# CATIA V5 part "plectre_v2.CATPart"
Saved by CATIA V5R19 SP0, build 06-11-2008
Part number: plectre_v2
Bounding box of the stored display mesh (mm): x 0 to 29, y 0 to 25.001, z 0 to 25.001
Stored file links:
  C:\Users\Rémi\Documents\BTS CPI\Projet 04- Guitar Elec\Maquette 3D\Système Médiator\plectre_v2.CATPart
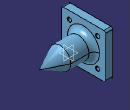
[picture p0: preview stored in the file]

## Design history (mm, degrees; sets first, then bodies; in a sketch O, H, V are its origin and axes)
Body1 (main body)
  Sketch1 on yz-plane, origin (0, 0, 0), H (0, 1, 0), V (0, 0, 1)
    line L1 (0, 25.001) -> (25.001, 25.001)
    line L2 (25.001, 25.001) -> (25.001, 0)
    line L3 (25.001, 0) -> (0, 0)
    line L4 (0, 0) -> (0, 25.001)
    point P4 (0, 0)
    length L1 = 25.001
    length L2 = 25.001
    distance P4 V = 0
    distance L3 H = 0
    horizontal: L1 H, L3 H
    vertical: L2 V, L4 V
  Pad1: profile Sketch1, direction (1, 0, 0), length 4
  Sketch2 on end face of Pad1, origin (4, 0, 0), H (0, 1, 0), V (0, 0, 1)
    circle A1 centre (20.501, 4.501) radius 1
    point P1 (20.501, 4.501)
    reference projected line E1 (0, 0) -> (25.001, 0) from edge [face of Pad1 from Sketch1.L3 | end face of Pad1]
    reference projected line E2 (25.001, 0) -> (25.001, 25.001) from edge [face of Pad1 from Sketch1.L2 | end face of Pad1]
    point P2 (20.501, 20.501)
    circle A2 centre (20.501, 20.501) radius 1
    reference projected line E3 (25.001, 25.001) -> (0, 25.001) from edge [face of Pad1 from Sketch1.L1 | end face of Pad1]
    reference projected line E4 (25.001, 0) -> (25.001, 25.001) from edge [face of Pad1 from Sketch1.L2 | end face of Pad1]
    point P3 (4.5, 4.501)
    circle A3 centre (4.5, 4.501) radius 1
    reference projected line E5 (0, 0) -> (25.001, 0) from edge [face of Pad1 from Sketch1.L3 | end face of Pad1]
    reference projected line E6 (0, 25.001) -> (0, 0) from edge [face of Pad1 from Sketch1.L4 | end face of Pad1]
    point P4 (4.5, 20.501)
    circle A4 centre (4.5, 20.501) radius 1
    reference projected line E7 (25.001, 25.001) -> (0, 25.001) from edge [face of Pad1 from Sketch1.L1 | end face of Pad1]
    reference projected line E8 (0, 25.001) -> (0, 0) from edge [face of Pad1 from Sketch1.L4 | end face of Pad1]
    radius A1 = 1
    distance P1 E1 = 4.501
    distance P1 E2 = 4.5
    distance P2 E3 = 4.5
    distance P2 E4 = 4.5
    distance P3 E5 = 4.501
    distance P3 E6 = 4.5
    distance P4 E7 = 4.5
    distance P4 E8 = 4.5
  Pocket1: profile Sketch2, direction (-1, 0, 0), through (limit type 6)
  Chamfer1: length 0.2, angle 45, on edge [end face of Pad1 | face of Pocket1 from Sketch2.A1]; edge [end face of Pad1 | face of Pocket1 from Sketch2.A3]; edge [end face of Pad1 | face of Pocket1 from Sketch2.A4]; edge [end face of Pad1 | face of Pocket1 from Sketch2.A2]
  Fillet1: radius 1, on edge [face of Pad1 from Sketch1.L2 | face of Pad1 from Sketch1.L3]; edge [face of Pad1 from Sketch1.L3 | face of Pad1 from Sketch1.L4]; edge [face of Pad1 from Sketch1.L4 | face of Pad1 from Sketch1.L1]; edge [face of Pad1 from Sketch1.L1 | face of Pad1 from Sketch1.L2]
  Sketch3 on end face of Pad1, origin (4, 0, 0), H (0, 1, 0), V (0, 0, 1)
    circle A1 centre (12.501, 12.501) radius 6
    point P1 (12.501, 12.501)
    reference projected line E1 (25.001, 25.001) -> (0, 25.001) from edge [face of Pad1 from Sketch1.L1 | end face of Pad1]
    reference projected line E2 (25.001, 0) -> (25.001, 25.001) from edge [face of Pad1 from Sketch1.L2 | end face of Pad1]
    distance P1 E1 = 12.5
    distance P1 E2 = 12.5
    radius A1 = 6
  Pad2: profile Sketch3, direction (1, 0, 0), length 25
  Fillet2: radius 3, on edge [end face of Pad1 | face of Pad2 from Sketch3.A1]
  Chamfer2: length 6, angle 63, on end face of Pad2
